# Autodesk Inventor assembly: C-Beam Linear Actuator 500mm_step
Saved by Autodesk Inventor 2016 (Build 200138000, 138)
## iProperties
Created: 2016-03
Part Number: C-Beam Linear Actuator 500mm_step
Document SubType Name: Assembly
Designer: bongo_000
Author: bongo_000
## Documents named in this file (19)
- C:\Users\bongo_000\Downloads\DLP\C-Beam Linear Actuator 500mm_step.iam
- C:\Users\bongo_000\Downloads\DLP\Low Profile Screw M5_M5 x 25.ipt
- C:\Users\bongo_000\Downloads\DLP\Flexible Coupling 0.25in x 8mm.ipt
- C:\Users\bongo_000\Downloads\DLP\C-Beam 40x80x500 Linear Rail.ipt
- C:\Users\bongo_000\Downloads\DLP\Xtreme Mini V Wheel_Eccentric.iam
- C:\Users\bongo_000\Downloads\DLP\Nylon Insert Lock Nut M5.ipt
- C:\Users\bongo_000\Downloads\DLP\Lock Collar 8mm.ipt
- C:\Users\bongo_000\Downloads\DLP\8mm Acme Nut Block.ipt
- C:\Users\bongo_000\Downloads\DLP\Low Profile Screw M5_M5 x 20.ipt
- C:\Users\bongo_000\Downloads\DLP\Ball Bearing 8 x 16 x 5.ipt
- C:\Users\bongo_000\Downloads\DLP\Nema 23 Stepper Motor.ipt
- C:\Users\bongo_000\Downloads\DLP\C-Beam End Mount.ipt
- C:\Users\bongo_000\Downloads\DLP\C-Beam Gantry Plate.ipt
- C:\Users\bongo_000\Downloads\DLP\Aluminum Spacer 3mm.ipt
- C:\Users\bongo_000\Downloads\DLP\Aluminum Spacer 40mm.ipt
- C:\Users\bongo_000\Downloads\DLP\Low Profile Screw M5_M5 x 55.ipt
- C:\Users\bongo_000\Downloads\DLP\Xtreme Mini V Wheel_Straight.iam
- C:\Users\bongo_000\Downloads\DLP\Shim Washer 8mm.ipt
- C:\Users\bongo_000\Downloads\DLP\8mm leadscrew 540mm.ipt
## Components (40 placed, 40 different names)
1. Low Profile Screw M5_M5 x 25_1021
2. Flexible Coupling 0.25in x 8mm_1022
3. C-Beam 40x80x500 Linear Rail_1023
4. Xtreme Mini V Wheel_Eccentric_1024 [sub-assembly]
5. Nylon Insert Lock Nut M5_1025
6. Lock Collar 8mm_1026
7. Low Profile Screw M5_M5 x 25_1027
8. 8mm Acme Nut Block_1028
9. Low Profile Screw M5_M5 x 20_1029
10. Ball Bearing 8 x 16 x 5_1030
11. Low Profile Screw M5_M5 x 20_1031
12. Low Profile Screw M5_M5 x 20_1032
13. Nema 23 Stepper Motor_1033
14. C-Beam End Mount_1034
15. Xtreme Mini V Wheel_Eccentric_1035 [sub-assembly]
16. Low Profile Screw M5_M5 x 20_1036
17. Lock Collar 8mm_1037
18. Low Profile Screw M5_M5 x 25_1038
19. C-Beam Gantry Plate_1039
20. Low Profile Screw M5_M5 x 20_1040
21. Ball Bearing 8 x 16 x 5_1041
22. Aluminum Spacer 3mm_1042
23. Low Profile Screw M5_M5 x 20_1043
24. Low Profile Screw M5_M5 x 20_1044
25. Aluminum Spacer 40mm_1045
26. Low Profile Screw M5_M5 x 55_1046
27. Xtreme Mini V Wheel_Straight_1047 [sub-assembly]
28. Low Profile Screw M5_M5 x 20_1048
29. Shim Washer 8mm_1049
30. Low Profile Screw M5_M5 x 25_1050
31. 8mm leadscrew 540mm_1051
32. C-Beam End Mount_1052
33. Aluminum Spacer 3mm_1053
34. Nylon Insert Lock Nut M5_1054
35. Low Profile Screw M5_M5 x 20_1055
36. Aluminum Spacer 40mm_1056
37. Low Profile Screw M5_M5 x 55_1057
38. Xtreme Mini V Wheel_Straight_1058 [sub-assembly]
39. Low Profile Screw M5_M5 x 20_1059
40. Shim Washer 8mm_1060
